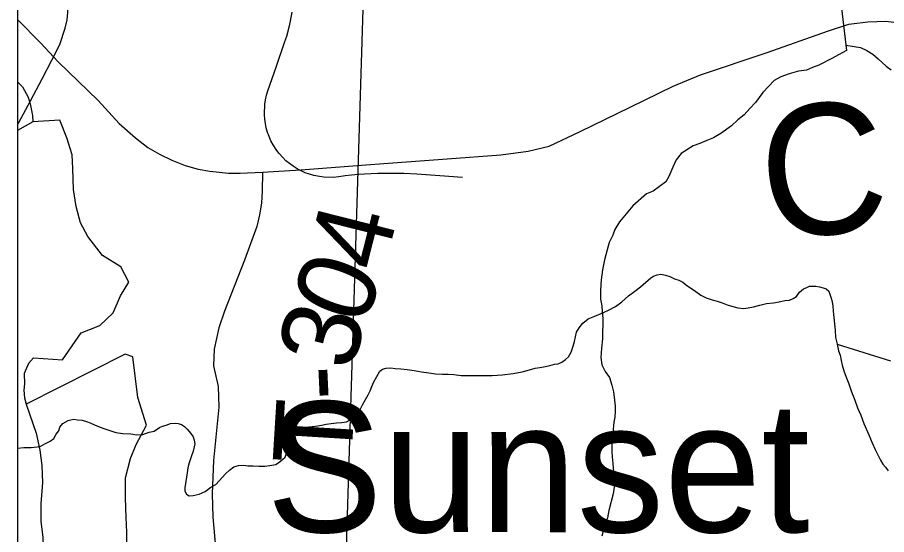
# Model space of a CAD drawing. Extents: x -6.1 to 38, y -7.7 to 22.
# Drawn here: x 2.1 to 2.73, y 18.414 to 18.789 of the extents above; entities that cross this region are included whole.
import ezdxf

# ---------------------------------------------------------------- set-up
doc = ezdxf.new("R2010")
doc.units = 0
for name, color, linetype in [('GM_X_Corporation', 7, 'Continuous'), ('GM_X_County_Road', 7, 'Continuous'), ('GM_X_Minor_Lake', 7, 'Continuous'), ('GM_X_Minor_Lake_Text', 7, 'Continuous'), ('GM_X_Minor_River', 7, 'Continuous'), ('GM_X_Minor_River_Text', 7, 'Continuous'), ('GM_X_Township_Road', 7, 'Continuous'), ('GM_X_Township_Road_Text', 7, 'Continuous'), ('SH_Data', 7, 'Continuous')]:
    doc.layers.add(name, color=color, linetype=linetype)

msp = doc.modelspace()

# ---------------------------------------------------------------- linework, layer by layer
at = {"layer": 'GM_X_Corporation'}
for points in [[(2.1, 20.09414), (2.1, 15.06368), (2.27273, 15.0594), (2.84159, 15.04746)], [(2.1, 19.36551), (2.1, 14.52316), (2.69973, 14.52546), (2.99532, 14.5306)]]:
    msp.add_lwpolyline(points, dxfattribs=at)
for points in [[(2.1, 19.08787), (2.1, 18.08314), (2.32853, 18.07616), (2.3594, 19.07674)], [(2.3594, 19.07674), (3.29403, 19.05339), (3.28738, 18.66674), (3.27769, 18.15146), (3.27494, 18.04606), (2.32853, 18.07616)]]:
    msp.add_lwpolyline(points, close=True, dxfattribs=at)
at = {"layer": 'GM_X_County_Road'}
for points in [[(2.1, 18.78766), (2.11673, 18.77067), (2.1296, 18.75696), (2.15855, 18.72886), (2.17393, 18.71208), (2.18554, 18.70187), (2.19449, 18.69487), (2.20302, 18.68998), (2.2121, 18.68551), (2.22175, 18.68173), (2.23112, 18.67907), (2.23951, 18.67754), (2.25322, 18.67614), (2.26146, 18.67614), (2.27769, 18.67698), (2.30566, 18.67866), (2.35264, 18.68229), (2.41165, 18.68649), (2.45052, 18.68956), (2.47049, 18.692), (2.48562, 18.69564), (2.50811, 18.70642), (2.54449, 18.72399), (2.57559, 18.73924), (2.59543, 18.74754), (2.64365, 18.76369), (2.68748, 18.77915), (2.70294, 18.78423), (2.70492, 18.78449)], [(2.70492, 18.78449), (2.71678, 18.78607), (2.7297, 18.78653), (2.74331, 18.78469), (2.77769, 18.77523)]]:
    msp.add_lwpolyline(points, dxfattribs=at)
at = {"layer": 'GM_X_Minor_Lake'}
msp.add_line((2.11131, 18.71349), (2.1, 18.70716), dxfattribs=at)
for points in [[(2.11175, 18.54218), (2.13279, 18.54073), (2.14625, 18.56015), (2.15982, 18.56554), (2.16957, 18.57469), (2.17478, 18.58723), (2.18075, 18.59712), (2.17501, 18.60808), (2.16173, 18.61634), (2.15106, 18.63029), (2.1457, 18.64012), (2.14259, 18.65185), (2.14062, 18.66434), (2.14014, 18.6795), (2.13969, 18.68935), (2.13582, 18.70183), (2.13082, 18.71469), (2.11131, 18.71349)], [(2.17944, 18.40572), (2.17937, 18.41557), (2.17892, 18.42618), (2.17844, 18.44058), (2.17834, 18.45498), (2.18202, 18.46903), (2.18611, 18.47928), (2.19356, 18.49335), (2.18738, 18.5134), (2.18377, 18.54294), (2.17809, 18.5448), (2.10625, 18.50842)], [(2.10625, 18.50842), (2.11351, 18.48755), (2.11625, 18.47506), (2.11783, 18.46408), (2.1183, 18.45158), (2.11689, 18.43603), (2.11698, 18.42352), (2.11857, 18.41178), (2.11904, 18.39966), (2.11949, 18.38867), (2.11847, 18.37312), (2.11591, 18.36098), (2.11411, 18.3477), (2.11269, 18.33405), (2.11318, 18.31813), (2.11215, 18.3041), (2.10582, 18.29118), (2.1, 18.28428)]]:
    msp.add_lwpolyline(points, dxfattribs=at)
at = {"layer": 'GM_X_Minor_River'}
for points in [[(2.69332, 18.83296), (2.7012, 18.76515), (2.69027, 18.75904), (2.68122, 18.75445), (2.6767, 18.75292), (2.67217, 18.751), (2.66651, 18.75022), (2.65972, 18.7483), (2.65368, 18.746), (2.64878, 18.74333), (2.64051, 18.73458), (2.63526, 18.72735), (2.63112, 18.72317), (2.62699, 18.7186), (2.62247, 18.71479), (2.61796, 18.71061)], [(2.70076, 18.76893), (2.71139, 18.76746), (2.71593, 18.76521), (2.72048, 18.76257), (2.72427, 18.75918), (2.72996, 18.75389), (2.73375, 18.75126)], [(2.1, 18.74248), (2.10364, 18.73886), (2.10783, 18.73129), (2.10936, 18.72637), (2.11091, 18.71804), (2.11131, 18.71349)], [(2.61796, 18.71061), (2.61005, 18.70489), (2.60478, 18.70184), (2.59988, 18.69992), (2.59497, 18.69763), (2.59007, 18.69609), (2.58141, 18.69037), (2.57765, 18.68581), (2.57541, 18.68049), (2.57242, 18.67366), (2.57017, 18.66986), (2.56114, 18.663), (2.55623, 18.66108), (2.54645, 18.65233), (2.54157, 18.64662), (2.53669, 18.64092), (2.53331, 18.63522), (2.53182, 18.63104), (2.5292, 18.62573), (2.52772, 18.62041), (2.52586, 18.61321), (2.52438, 18.606), (2.52329, 18.59879), (2.52294, 18.59121), (2.52297, 18.58477), (2.52375, 18.57984), (2.52415, 18.57567), (2.52455, 18.57075), (2.52458, 18.56544), (2.52422, 18.56165), (2.52424, 18.55597), (2.52352, 18.54914), (2.52318, 18.54232), (2.52396, 18.53702), (2.52625, 18.5321), (2.52929, 18.52794), (2.53121, 18.52226), (2.53236, 18.51734), (2.53315, 18.51128), (2.53354, 18.50711), (2.53356, 18.50332), (2.53321, 18.49915), (2.53247, 18.49536), (2.53175, 18.48778), (2.53102, 18.48285), (2.53106, 18.47413), (2.53145, 18.47034), (2.53185, 18.46541), (2.53226, 18.45935), (2.53304, 18.45405), (2.53306, 18.44988), (2.53196, 18.44343), (2.529, 18.43129), (2.52789, 18.42598), (2.52639, 18.42218), (2.52528, 18.41801), (2.5238, 18.4127)], [(2.23172, 18.44326), (2.23625, 18.44521), (2.2404, 18.44829), (2.2438, 18.45022), (2.24643, 18.45291), (2.25093, 18.4579), (2.25394, 18.46059), (2.25696, 18.4629), (2.26036, 18.46408), (2.26416, 18.46412), (2.26721, 18.46377), (2.27101, 18.4638), (2.2752, 18.46347), (2.27938, 18.46351), (2.28318, 18.46393), (2.28735, 18.46473), (2.29074, 18.46704), (2.29413, 18.47012), (2.2956, 18.47432), (2.29669, 18.47851), (2.29779, 18.48232), (2.29889, 18.48538), (2.30153, 18.48769), (2.30416, 18.48999), (2.30757, 18.49117), (2.31136, 18.49197), (2.3163, 18.4924), (2.32047, 18.4932), (2.32388, 18.49399), (2.32768, 18.49441), (2.33147, 18.49483), (2.33527, 18.49524), (2.33869, 18.49566), (2.34096, 18.49682), (2.34322, 18.49875), (2.34585, 18.50067), (2.3481, 18.50374), (2.35033, 18.50794), (2.35257, 18.51177), (2.35443, 18.51521), (2.35591, 18.51827), (2.35702, 18.52132), (2.3585, 18.52476), (2.36297, 18.53241), (2.36486, 18.53395), (2.36751, 18.53473), (2.37093, 18.53477), (2.37397, 18.53442), (2.37816, 18.53408), (2.38272, 18.53374), (2.38768, 18.53303), (2.39301, 18.53194), (2.39834, 18.53124), (2.40329, 18.53053), (2.40824, 18.53019), (2.41242, 18.53024), (2.4166, 18.5299), (2.42193, 18.52919), (2.42649, 18.52923), (2.43144, 18.52929), (2.43714, 18.52934), (2.44436, 18.52941), (2.45158, 18.52987), (2.45955, 18.5307), (2.466, 18.53191), (2.4713, 18.53348), (2.47547, 18.53467), (2.47889, 18.53508), (2.48306, 18.53588), (2.48609, 18.53667), (2.48951, 18.53747), (2.49216, 18.53787), (2.49481, 18.53904), (2.49745, 18.54097), (2.49971, 18.54289), (2.50157, 18.54633), (2.50304, 18.55053), (2.50414, 18.55396), (2.50486, 18.55739), (2.50558, 18.56082), (2.50744, 18.56388), (2.51007, 18.56733), (2.51383, 18.57041), (2.51875, 18.57236), (2.52329, 18.57431), (2.52859, 18.57664), (2.53388, 18.57936), (2.5384, 18.58283), (2.54329, 18.58706), (2.54781, 18.59052), (2.55196, 18.59361), (2.55949, 18.60015), (2.56137, 18.60131), (2.56402, 18.60247), (2.56668, 18.60288), (2.57011, 18.60215), (2.57316, 18.60104), (2.5766, 18.59956), (2.57965, 18.59845), (2.58271, 18.59696), (2.5854, 18.5947)], [(2.5854, 18.5947), (2.58885, 18.59245), (2.59192, 18.5902), (2.59575, 18.58758), (2.59957, 18.58572), (2.60377, 18.58424), (2.60758, 18.58313), (2.61102, 18.58203), (2.61484, 18.58054), (2.61713, 18.5798), (2.6198, 18.57907), (2.62247, 18.57834), (2.62665, 18.578), (2.63007, 18.57841), (2.63386, 18.57921), (2.63841, 18.5804), (2.64334, 18.58158), (2.64827, 18.58201), (2.65244, 18.58282), (2.65662, 18.58362), (2.66003, 18.58403), (2.66268, 18.5852), (2.66495, 18.58674), (2.66719, 18.58981), (2.67021, 18.59212), (2.67247, 18.59328), (2.67436, 18.59406), (2.67703, 18.59409), (2.67893, 18.59411), (2.68159, 18.59376), (2.68426, 18.59302), (2.68655, 18.59228), (2.68847, 18.5904), (2.68965, 18.58699), (2.69044, 18.58472), (2.69085, 18.58244), (2.69126, 18.57978), (2.69168, 18.57598), (2.69298, 18.56231), (2.69342, 18.55698), (2.69462, 18.55205), (2.69544, 18.54712), (2.69661, 18.54409), (2.69742, 18.54029), (2.69822, 18.53688), (2.69941, 18.53271), (2.70098, 18.52816), (2.70294, 18.52323), (2.70491, 18.51755), (2.70726, 18.51149), (2.70922, 18.50581), (2.71157, 18.50051), (2.71392, 18.49444), (2.71743, 18.48611), (2.71978, 18.48043), (2.72212, 18.47551), (2.72407, 18.47173), (2.72601, 18.46794), (2.72757, 18.46492), (2.72949, 18.46265), (2.73143, 18.46001)], [(2.69462, 18.55205), (2.73316, 18.53989)], [(2.11175, 18.54218), (2.10799, 18.53799), (2.105, 18.53078), (2.10504, 18.5232), (2.10468, 18.51865), (2.10509, 18.51297), (2.10625, 18.50842)], [(2.1, 18.47667), (2.10473, 18.47698), (2.11005, 18.47704), (2.1165, 18.47786), (2.1199, 18.4798), (2.12368, 18.48174), (2.12632, 18.48366), (2.12819, 18.48672), (2.13006, 18.48902), (2.13079, 18.49169), (2.13304, 18.49438), (2.13682, 18.4967), (2.13871, 18.4971), (2.14099, 18.4975), (2.14365, 18.49714), (2.14708, 18.4968), (2.15089, 18.4957), (2.15318, 18.49458), (2.15586, 18.49346), (2.15891, 18.49235), (2.16273, 18.49087), (2.16693, 18.48939), (2.17151, 18.48791), (2.17646, 18.4872), (2.18217, 18.48688), (2.18674, 18.48616), (2.19091, 18.48658), (2.19546, 18.48815), (2.19925, 18.48895), (2.20302, 18.49165), (2.20529, 18.49243), (2.20794, 18.49322), (2.21097, 18.49439), (2.21439, 18.4948), (2.21667, 18.49445), (2.21896, 18.49371), (2.22126, 18.49221), (2.22318, 18.49033), (2.22588, 18.48731), (2.22743, 18.48467), (2.22822, 18.48239), (2.22863, 18.47973), (2.22828, 18.47745), (2.22755, 18.4744), (2.22608, 18.4702), (2.22461, 18.46601), (2.22351, 18.46219), (2.22317, 18.45876), (2.2214, 18.44772), (2.22143, 18.44544), (2.22259, 18.44317), (2.2245, 18.44205), (2.22755, 18.44208), (2.23172, 18.44326)]]:
    msp.add_lwpolyline(points, dxfattribs=at)
at = {"layer": 'GM_X_Township_Road'}
for points in [[(2.1, 18.71094), (2.10106, 18.7129), (2.10956, 18.72874), (2.11805, 18.74459), (2.12489, 18.75804), (2.13075, 18.76957), (2.13476, 18.78133), (2.13622, 18.78744), (2.13658, 18.79271), (2.13622, 18.80625), (2.13722, 18.82295), (2.13986, 18.83935), (2.14175, 18.84946), (2.14022, 18.87574), (2.13984, 18.88003)], [(2.4228, 18.67299), (2.40627, 18.67418), (2.38973, 18.67537), (2.38026, 18.67588), (2.37552, 18.67601), (2.36131, 18.67591), (2.35657, 18.67571), (2.35183, 18.67543), (2.34714, 18.67507), (2.3424, 18.67462), (2.33771, 18.67409), (2.33302, 18.67349), (2.32899, 18.6731), (2.32236, 18.67321), (2.31909, 18.67361), (2.31506, 18.67443), (2.31184, 18.67535), (2.30876, 18.67647), (2.30573, 18.67783), (2.30279, 18.67938), (2.3, 18.68112), (2.29735, 18.68306), (2.29479, 18.68518), (2.29242, 18.68748), (2.28967, 18.69058), (2.28769, 18.69322), (2.28546, 18.6967), (2.2839, 18.69963), (2.28257, 18.70265), (2.28144, 18.70576), (2.28054, 18.70893), (2.27983, 18.71216), (2.27935, 18.71544), (2.27912, 18.71874), (2.27945, 18.72616), (2.27998, 18.72943), (2.28074, 18.73266), (2.28169, 18.73582), (2.28785, 18.75375), (2.29402, 18.77167), (2.2953, 18.77562), (2.29711, 18.78211), (2.29815, 18.78647), (2.29939, 18.79309)], [(2.27769, 18.67698), (2.2775, 18.66315), (2.27702, 18.65445), (2.27556, 18.64598), (2.27363, 18.63752), (2.26468, 18.6131), (2.25017, 18.5761), (2.24607, 18.56377), (2.24268, 18.54829), (2.2422, 18.53619), (2.24558, 18.5212), (2.24607, 18.50621), (2.2422, 18.46752), (2.24123, 18.44334), (2.24171, 18.42641), (2.24364, 18.40489)]]:
    msp.add_lwpolyline(points, dxfattribs=at)
at = {"layer": 'SH_Data'}
msp.add_line((2.1, 20.9), (2.1, 14.1), dxfattribs=at)

# ---------------------------------------------------------------- texts
at = {"layer": 'GM_X_Minor_Lake_Text'}
msp.add_text('Sunset', height=0.094694, rotation=359.98538, dxfattribs=at).set_placement((2.28042, 18.41563))
at = {"layer": 'GM_X_Minor_River_Text'}
msp.add_text('Creek', height=0.094761, rotation=5.39369, dxfattribs=at).set_placement((2.64313, 18.62759))
at = {"layer": 'GM_X_Township_Road_Text'}
for s, rotation, p in [('4', 75.78294, (2.36535, 18.60309)), ('0', 69.34954, (2.35092, 18.56371)), ('3', 76.00793, (2.34298, 18.53141)), ('-', 92.63135, (2.34448, 18.51243)), ('T', 86.4921, (2.34183, 18.46337))]:
    msp.add_text(s, height=0.05682, rotation=rotation, dxfattribs=at).set_placement(p)

doc.saveas('drawing.dxf')
